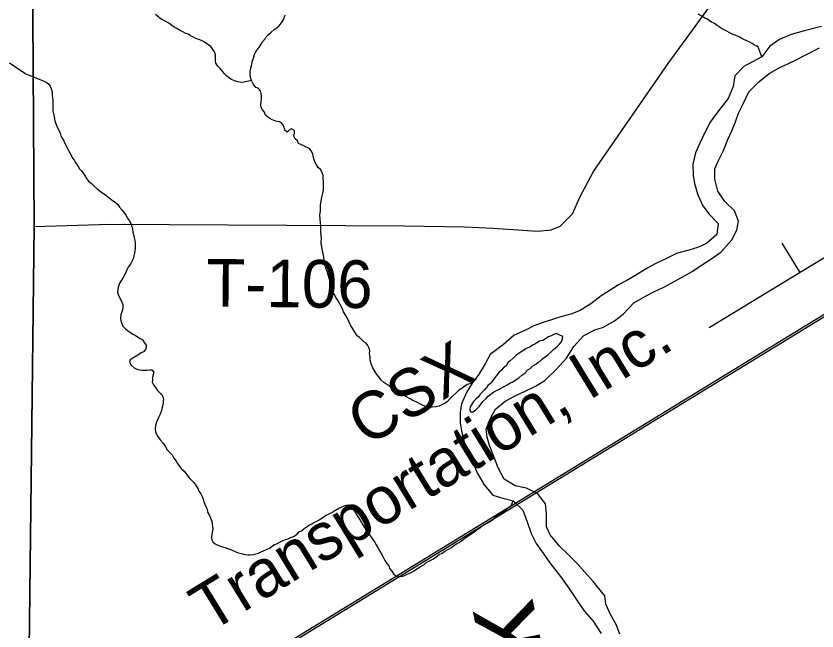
# Model space of a CAD drawing. Extents: x -7.3 to 34, y 0 to 22.
# Drawn here: x 2.725 to 3.68, y 18.213 to 18.947 of the extents above; entities that cross this region are included whole.
import ezdxf

# ---------------------------------------------------------------- set-up
doc = ezdxf.new("R2010")
doc.units = 0
for name, color, linetype in [('GM_X_Corporation', 7, 'Continuous'), ('GM_X_Major_River', 7, 'Continuous'), ('GM_X_Major_River_Text', 7, 'Continuous'), ('GM_X_Minor_River', 7, 'Continuous'), ('GM_X_Rail_Line', 7, 'Continuous'), ('GM_X_Rail_Line_Text', 7, 'Continuous'), ('GM_X_Township_Road', 7, 'Continuous'), ('GM_X_Township_Road_Text', 7, 'Continuous')]:
    doc.layers.add(name, color=color, linetype=linetype)

msp = doc.modelspace()

# ---------------------------------------------------------------- linework, layer by layer
at = {"layer": 'GM_X_Corporation'}
for points in [[(2.72526, 17.27857), (2.73186, 17.61235), (2.73309, 17.68446), (2.73436, 17.75863), (2.73656, 17.91355), (2.7405, 18.19145), (2.74664, 18.69646), (2.74012, 19.69659), (2.7402, 19.71066)], [(2.7402, 19.71066), (2.74012, 19.69659), (2.74664, 18.69646), (2.7405, 18.19145), (2.73656, 17.91355), (2.73436, 17.75863), (2.73309, 17.68446), (2.73186, 17.61235), (2.72526, 17.27857)], [(2.72526, 17.27857), (2.73186, 17.61235), (2.73309, 17.68446), (2.73436, 17.75863), (2.73656, 17.91355), (2.7405, 18.19145), (2.74664, 18.69646), (2.74012, 19.69659), (2.7402, 19.71066)], [(2.7402, 19.71066), (2.74012, 19.69659), (2.74664, 18.69646), (2.7405, 18.19145), (2.73656, 17.91355), (2.73436, 17.75863), (2.73309, 17.68446), (2.73186, 17.61235), (2.72526, 17.27857)]]:
    msp.add_lwpolyline(points, dxfattribs=at)
at = {"layer": 'GM_X_Major_River'}
for points in [[(3.68592, 18.93456), (3.67562, 18.93216), (3.66378, 18.92904), (3.64965, 18.92522), (3.63546, 18.91912), (3.62426, 18.91105), (3.61445, 18.89838), (3.6033, 18.89258), (3.59291, 18.88677), (3.58238, 18.87563), (3.58054, 18.86314), (3.57448, 18.84886)], [(3.44524, 18.2095), (3.44061, 18.22102), (3.43409, 18.23296), (3.42835, 18.24527), (3.4271, 18.25557), (3.41351, 18.27263), (3.40355, 18.28352), (3.39435, 18.29402), (3.38436, 18.30377), (3.37327, 18.3147), (3.36187, 18.32828), (3.35757, 18.3379), (3.35758, 18.3531), (3.35638, 18.36529), (3.34684, 18.37769), (3.33373, 18.38373), (3.32015, 18.38673), (3.30709, 18.39466), (3.30023, 18.40813), (3.2949, 18.42157), (3.28955, 18.43463), (3.28677, 18.44458), (3.28588, 18.45411), (3.29117, 18.46803), (3.29674, 18.47816), (3.30837, 18.48774), (3.32105, 18.49426), (3.33219, 18.49968), (3.34447, 18.50545), (3.35565, 18.51239), (3.36965, 18.52572), (3.38137, 18.53911), (3.39046, 18.55294), (3.40217, 18.56595), (3.41524, 18.57283), (3.42556, 18.57599), (3.43865, 18.58364), (3.44909, 18.59136), (3.46196, 18.6051), (3.47659, 18.61347), (3.48658, 18.61854), (3.49694, 18.62321), (3.51079, 18.63084), (3.52156, 18.63665), (3.53157, 18.64248), (3.54392, 18.65053), (3.55357, 18.65712), (3.56554, 18.66556), (3.57881, 18.68005), (3.5848, 18.69167), (3.5866, 18.70227), (3.58199, 18.71492), (3.57052, 18.72585), (3.56212, 18.73822), (3.55832, 18.75238), (3.55865, 18.76491), (3.56269, 18.77469), (3.56869, 18.78669), (3.57396, 18.79986), (3.57879, 18.81037), (3.58323, 18.8209), (3.58691, 18.83107), (3.59173, 18.84158), (3.59895, 18.8566), (3.61102, 18.86883), (3.62342, 18.87877), (3.63534, 18.88531), (3.65223, 18.89324), (3.66799, 18.9012), (3.68336, 18.90917)], [(3.57448, 18.84886), (3.56272, 18.83396), (3.55289, 18.82053), (3.5465, 18.80815), (3.54048, 18.79539), (3.53562, 18.78373), (3.53225, 18.77052), (3.53266, 18.75721), (3.5343, 18.74729), (3.53812, 18.73389), (3.54422, 18.72082), (3.55155, 18.71075), (3.56263, 18.69945), (3.56078, 18.68658), (3.54837, 18.67587), (3.53762, 18.67083), (3.5273, 18.66767), (3.51279, 18.66385), (3.50165, 18.65844), (3.48744, 18.65157), (3.47666, 18.64538), (3.46318, 18.63737), (3.45355, 18.63153), (3.44356, 18.62646), (3.43237, 18.61914), (3.42274, 18.61331), (3.41074, 18.60373), (3.39801, 18.59569), (3.3869, 18.59141), (3.37584, 18.58865), (3.36589, 18.58548), (3.3548, 18.58196), (3.34255, 18.57733), (3.33256, 18.57226), (3.31914, 18.56652), (3.30634, 18.55544), (3.29047, 18.5433), (3.28449, 18.53205), (3.27657, 18.51895), (3.26911, 18.50926), (3.26277, 18.49877), (3.25633, 18.48449), (3.25456, 18.47466), (3.2546, 18.46173), (3.25625, 18.45219), (3.25897, 18.43996), (3.26356, 18.42692), (3.27004, 18.41384), (3.2754, 18.40116), (3.2834, 18.38766), (3.2937, 18.37561), (3.30574, 18.37189), (3.31779, 18.36855), (3.32964, 18.3576), (3.33459, 18.3438), (3.33953, 18.32961), (3.34529, 18.31768), (3.35262, 18.30799), (3.36176, 18.29484), (3.37423, 18.27856), (3.38448, 18.26462), (3.39324, 18.25148), (3.40237, 18.23795), (3.41341, 18.22512), (3.42289, 18.21044)], [(3.36927, 18.56821), (3.36659, 18.56713), (3.36315, 18.56568), (3.36008, 18.56423), (3.35662, 18.56202), (3.35316, 18.5602), (3.34935, 18.55913), (3.34627, 18.5573), (3.34358, 18.55546), (3.3409, 18.55437), (3.33782, 18.55216), (3.33361, 18.55035), (3.33053, 18.54852), (3.32746, 18.54668), (3.32476, 18.54446), (3.32129, 18.54225), (3.31781, 18.53891), (3.31433, 18.53594), (3.31162, 18.53334), (3.30965, 18.52996), (3.30656, 18.52736), (3.30346, 18.52439), (3.30075, 18.52178), (3.29879, 18.51916), (3.29607, 18.5158), (3.29372, 18.51243), (3.29137, 18.50906), (3.2879, 18.50647), (3.28595, 18.50385), (3.28323, 18.50087), (3.2809, 18.49826), (3.27779, 18.4949), (3.27622, 18.49227), (3.27351, 18.49005), (3.2708, 18.48745), (3.26845, 18.48408), (3.26648, 18.4807), (3.26641, 18.47766), (3.26711, 18.47498), (3.26977, 18.47492), (3.27284, 18.47675), (3.27788, 18.48159), (3.27984, 18.48459), (3.28179, 18.48721), (3.28567, 18.49093), (3.288, 18.49354), (3.29147, 18.49612), (3.29494, 18.49871), (3.29801, 18.50055), (3.30146, 18.50199), (3.30415, 18.50345), (3.30799, 18.50565), (3.31067, 18.50712), (3.31413, 18.50894), (3.31758, 18.51077), (3.32027, 18.51261), (3.32451, 18.51556), (3.32837, 18.51852), (3.33184, 18.52111), (3.33533, 18.52484), (3.33803, 18.52668), (3.3415, 18.52965), (3.34496, 18.53185), (3.34767, 18.53407), (3.35036, 18.53592), (3.35307, 18.53814), (3.35615, 18.54035), (3.35963, 18.54332), (3.36311, 18.54667), (3.36659, 18.54963), (3.37007, 18.5526), (3.37278, 18.5552), (3.37551, 18.55857), (3.37672, 18.56196), (3.37716, 18.56462)], [(3.37716, 18.56462), (3.36927, 18.56821)]]:
    msp.add_lwpolyline(points, dxfattribs=at)
at = {"layer": 'GM_X_Minor_River'}
for points in [[(3.00562, 18.87042), (2.99723, 18.86832), (2.99381, 18.86802), (2.98965, 18.86849), (2.98551, 18.86972), (2.98213, 18.87131), (2.97876, 18.87329), (2.97615, 18.87562), (2.97356, 18.87834), (2.97135, 18.88143), (2.96838, 18.88454), (2.96578, 18.88726), (2.9632, 18.89073), (2.9629, 18.89416), (2.96296, 18.89682), (2.96267, 18.90101), (2.96161, 18.90445), (2.9594, 18.90792), (2.95719, 18.91063), (2.95346, 18.91376), (2.94897, 18.91652), (2.94597, 18.9181), (2.94296, 18.9193), (2.93958, 18.92052), (2.93657, 18.92173), (2.9332, 18.9237), (2.9302, 18.92567), (2.92757, 18.92648), (2.92382, 18.92847), (2.92082, 18.93005), (2.9167, 18.93242), (2.9137, 18.93401), (2.9107, 18.93597), (2.90735, 18.93871), (2.9021, 18.94148), (2.89797, 18.94347), (2.89387, 18.9466), (2.89126, 18.94894)], [(3.08865, 18.76368), (3.0853, 18.76641), (3.08347, 18.76949), (3.08164, 18.77258), (3.08021, 18.77679), (3.07953, 18.78023), (3.07883, 18.7829), (3.07701, 18.78637), (3.07479, 18.78908), (3.07178, 18.79028), (3.06803, 18.79226), (3.0654, 18.79346), (3.06202, 18.79505), (3.06057, 18.79813), (3.05797, 18.80047), (3.05615, 18.80393), (3.05698, 18.80733), (3.05705, 18.81075), (3.05368, 18.81273), (3.05099, 18.81127), (3.04828, 18.80866), (3.04568, 18.811), (3.04461, 18.81407), (3.04353, 18.81675), (3.0417, 18.81983), (3.03907, 18.82103), (3.03491, 18.82188), (3.03039, 18.82312), (3.02777, 18.8247), (3.02516, 18.82666), (3.02255, 18.82899), (3.02111, 18.83245), (3.01889, 18.83516), (3.01743, 18.83785), (3.01674, 18.84091), (3.01721, 18.84508), (3.01767, 18.84849), (3.01773, 18.85153), (3.01742, 18.85458), (3.01636, 18.85802), (3.01377, 18.86112), (3.01113, 18.86194), (3.00781, 18.86619), (3.00562, 18.87042), (3.00456, 18.87387), (3.00427, 18.87805), (3.00434, 18.88109), (3.00518, 18.88488), (3.00561, 18.88753), (3.00605, 18.89018), (3.00689, 18.89359), (3.0081, 18.89698), (3.00932, 18.90114), (3.01052, 18.90377), (3.01209, 18.9064), (3.01443, 18.90939), (3.01718, 18.91351), (3.01876, 18.91652), (3.02225, 18.91987), (3.02344, 18.9225), (3.02615, 18.9251), (3.02924, 18.9277), (3.03273, 18.93104), (3.03542, 18.9325), (3.03889, 18.93547), (3.04123, 18.93846), (3.04358, 18.94183), (3.04479, 18.94523), (3.04639, 18.94861)], [(3.61445, 18.89838), (3.60972, 18.91109), (3.60807, 18.9113), (3.60545, 18.91287), (3.60283, 18.91445), (3.60021, 18.91603), (3.59683, 18.91762), (3.59382, 18.91883), (3.59082, 18.92042), (3.5882, 18.92199), (3.58482, 18.92359), (3.58143, 18.9248), (3.57843, 18.92601), (3.57543, 18.92759), (3.57281, 18.92917), (3.56943, 18.93077), (3.56606, 18.93274), (3.56119, 18.93589), (3.55821, 18.93823), (3.55445, 18.93984), (3.5496, 18.94336), (3.54659, 18.94457), (3.54285, 18.94693), (3.53873, 18.9493)], [(2.73528, 18.87839), (2.71731, 18.89074)], [(2.73528, 18.87839), (2.7583, 18.86933), (2.76093, 18.86813), (2.76354, 18.86618), (2.76576, 18.86347), (2.76719, 18.85964), (2.76787, 18.85582), (2.76817, 18.85239), (2.7685, 18.84972), (2.76882, 18.84705), (2.76874, 18.84325), (2.76868, 18.84059), (2.76897, 18.83679), (2.76892, 18.83412), (2.76959, 18.83031), (2.77029, 18.82725), (2.77099, 18.82458), (2.77131, 18.82191), (2.77273, 18.81769), (2.77454, 18.81385), (2.776, 18.81078), (2.77744, 18.80733), (2.77851, 18.80426), (2.77997, 18.80157), (2.78179, 18.79811), (2.78324, 18.79503), (2.7847, 18.79234), (2.78615, 18.78927), (2.78761, 18.78657), (2.78907, 18.78388), (2.79053, 18.78119), (2.79235, 18.77772), (2.79419, 18.77502), (2.79602, 18.77232), (2.7986, 18.76846), (2.8008, 18.76499), (2.80339, 18.76189), (2.80522, 18.75919), (2.80743, 18.7561), (2.80889, 18.75341), (2.81148, 18.75031), (2.81445, 18.74759), (2.81817, 18.74408), (2.8219, 18.74096), (2.82525, 18.73823), (2.82824, 18.73626), (2.83197, 18.73352), (2.83608, 18.73038), (2.84018, 18.72725), (2.84317, 18.72491), (2.84577, 18.72257), (2.84835, 18.71909), (2.85169, 18.7156), (2.85353, 18.7129), (2.85574, 18.7098), (2.85756, 18.70634), (2.86014, 18.70287), (2.86196, 18.6994), (2.86302, 18.69596), (2.86372, 18.6929), (2.8644, 18.68946), (2.86509, 18.68641), (2.86577, 18.68259), (2.86646, 18.67953), (2.86715, 18.67609), (2.86707, 18.67267), (2.86701, 18.67001), (2.86658, 18.66736), (2.86613, 18.66433), (2.8653, 18.66092), (2.86484, 18.65751), (2.86327, 18.65488), (2.86129, 18.65112), (2.85856, 18.64738), (2.85697, 18.64437), (2.85577, 18.64136), (2.85418, 18.63797), (2.85261, 18.63534), (2.85064, 18.63196), (2.84829, 18.62859), (2.84747, 18.62595), (2.84666, 18.6233), (2.84622, 18.62065), (2.84615, 18.61761), (2.84686, 18.61493), (2.84793, 18.61224), (2.84975, 18.6084), (2.85121, 18.60571), (2.85229, 18.60302), (2.85221, 18.59922), (2.85177, 18.59657), (2.85056, 18.59317), (2.85012, 18.59052), (2.84967, 18.58711), (2.84997, 18.58368), (2.85103, 18.58023), (2.85248, 18.57716), (2.85545, 18.57405), (2.85807, 18.57209), (2.86143, 18.56974)], [(3.26911, 18.50926), (3.26289, 18.50739), (3.26019, 18.50555), (3.25711, 18.50334), (3.25287, 18.50039), (3.24978, 18.49779), (3.2463, 18.49444), (3.2428, 18.49072), (3.23969, 18.48736), (3.23699, 18.48514), (3.23355, 18.48369), (3.22971, 18.48149), (3.22552, 18.48082), (3.22134, 18.48053), (3.21868, 18.48021), (3.21453, 18.48106), (3.21077, 18.48267), (3.20663, 18.48428), (3.20288, 18.48626), (3.20026, 18.48784), (3.19763, 18.48904), (3.19501, 18.49062), (3.19051, 18.49299), (3.18602, 18.49575), (3.1834, 18.49771), (3.17966, 18.4997), (3.17591, 18.50168), (3.17217, 18.50442), (3.16881, 18.50678), (3.16619, 18.50835), (3.16357, 18.50993), (3.16022, 18.51305), (3.15801, 18.51614), (3.15543, 18.51962), (3.15322, 18.52271), (3.15067, 18.52733), (3.1485, 18.53232), (3.1478, 18.53499), (3.14748, 18.53766), (3.14717, 18.54109), (3.14648, 18.54415), (3.14694, 18.54794), (3.14625, 18.551), (3.14442, 18.55408), (3.14258, 18.55679), (3.13996, 18.55836), (3.13736, 18.5607), (3.13476, 18.56342), (3.13178, 18.56577), (3.12922, 18.57001), (3.12628, 18.57463), (3.12444, 18.57734), (3.12226, 18.58195), (3.12082, 18.5854), (3.11827, 18.59002), (3.11571, 18.59426), (3.11426, 18.59771), (3.11281, 18.60078), (3.11136, 18.60386), (3.1088, 18.6081), (3.10696, 18.6108), (3.10477, 18.61465), (3.10295, 18.61849), (3.10151, 18.62195), (3.10049, 18.62729), (3.09981, 18.63073), (3.09836, 18.63418), (3.09767, 18.63724), (3.09553, 18.64337), (3.09445, 18.64606), (3.09376, 18.64949), (3.09346, 18.65292), (3.0924, 18.65675), (3.09142, 18.664), (3.09034, 18.66668), (3.0897, 18.67202), (3.08901, 18.67507), (3.08907, 18.67773), (3.08915, 18.68154), (3.08887, 18.6861), (3.08855, 18.68916), (3.08865, 18.69334), (3.08833, 18.69638), (3.08804, 18.70057), (3.08776, 18.70514), (3.08748, 18.70971), (3.08797, 18.71464), (3.08804, 18.71806), (3.08813, 18.72187), (3.08898, 18.72641), (3.08942, 18.72906), (3.09025, 18.73247), (3.09108, 18.73587), (3.09154, 18.73966), (3.0916, 18.74232), (3.09168, 18.74612), (3.09176, 18.74954), (3.09146, 18.75335), (3.09116, 18.75678), (3.09009, 18.76023), (3.08865, 18.76368)], [(2.86143, 18.56974), (2.86442, 18.56777), (2.86704, 18.5662), (2.86965, 18.56424), (2.87227, 18.56266), (2.87565, 18.56068), (2.87785, 18.55759), (2.88006, 18.5545), (2.88001, 18.55184), (2.87919, 18.5492), (2.87686, 18.54659), (2.87417, 18.54512), (2.87147, 18.54328), (2.8684, 18.54145), (2.86417, 18.53887), (2.8611, 18.53704), (2.86027, 18.53402), (2.8621, 18.53055), (2.86582, 18.52743), (2.8692, 18.52583), (2.87222, 18.52501), (2.87486, 18.52457), (2.8779, 18.52451), (2.88094, 18.52482), (2.88436, 18.52512), (2.88701, 18.52507), (2.88923, 18.52236), (2.888, 18.5182), (2.88756, 18.51555), (2.88751, 18.51289), (2.88745, 18.51023), (2.8889, 18.50715), (2.89111, 18.50406), (2.89331, 18.50059), (2.8959, 18.49787), (2.89925, 18.49476), (2.90068, 18.49054), (2.90062, 18.48788), (2.90056, 18.48522), (2.89973, 18.48181), (2.89891, 18.47879), (2.89807, 18.47539), (2.89686, 18.47199), (2.89528, 18.46898), (2.89368, 18.46521), (2.89208, 18.46144), (2.89126, 18.4588), (2.8908, 18.45462), (2.89148, 18.45119), (2.89255, 18.44812), (2.89401, 18.44543), (2.89696, 18.44156), (2.90029, 18.43769), (2.90286, 18.43383), (2.90505, 18.42959), (2.90839, 18.42648), (2.91099, 18.42376), (2.91317, 18.41953), (2.91613, 18.41604), (2.91759, 18.41335), (2.92016, 18.40949), (2.92238, 18.40678), (2.92536, 18.40405), (2.92868, 18.3998), (2.93164, 18.39631), (2.93422, 18.39321), (2.9372, 18.39048), (2.93977, 18.38662), (2.94234, 18.38276), (2.94304, 18.38009), (2.94525, 18.37699), (2.94708, 18.37391), (2.94815, 18.37085), (2.94884, 18.36741), (2.95029, 18.36472), (2.95137, 18.36203), (2.95283, 18.35895), (2.9535, 18.35514), (2.95533, 18.35205), (2.95677, 18.3486), (2.95858, 18.34438), (2.95888, 18.34095), (2.9592, 18.3379), (2.95951, 18.33485), (2.95906, 18.33144), (2.95862, 18.32878), (2.95817, 18.32537), (2.95848, 18.32232), (2.95956, 18.31963), (2.96254, 18.31729), (2.96629, 18.3153), (2.9712, 18.31405), (2.97383, 18.31324), (2.97722, 18.31202), (2.98061, 18.31081), (2.98362, 18.3096), (2.987, 18.30801), (2.99001, 18.3068), (2.9934, 18.30597), (2.99793, 18.30473), (3.00133, 18.30427)], [(3.00133, 18.30427), (3.00398, 18.30422), (3.00778, 18.30452), (3.01084, 18.30559), (3.01427, 18.30628), (3.01734, 18.30773), (3.02002, 18.30919), (3.02461, 18.31099), (3.02807, 18.31282), (3.03231, 18.31615), (3.03499, 18.31724), (3.03882, 18.31905), (3.04227, 18.32088), (3.04686, 18.32268), (3.04954, 18.32339), (3.05337, 18.3252), (3.05604, 18.32629), (3.06027, 18.32886), (3.06261, 18.33185), (3.06529, 18.33293), (3.06877, 18.3359), (3.07223, 18.33811), (3.07493, 18.33995), (3.07761, 18.34141), (3.0803, 18.34288), (3.08374, 18.34432), (3.08644, 18.34617), (3.09105, 18.34873), (3.09414, 18.35132), (3.09758, 18.35277), (3.1018, 18.35496), (3.10526, 18.35717), (3.10988, 18.36011), (3.11293, 18.36119), (3.11561, 18.36227), (3.11868, 18.36372), (3.1221, 18.36403), (3.12583, 18.36091), (3.12765, 18.35782), (3.12949, 18.35512), (3.13131, 18.35166), (3.13389, 18.34818), (3.13535, 18.34548), (3.13719, 18.34278), (3.13865, 18.34009), (3.14121, 18.33585), (3.14342, 18.33276), (3.146, 18.32928), (3.14784, 18.32658), (3.15041, 18.32272), (3.15262, 18.31963), (3.15444, 18.31616), (3.15738, 18.31154), (3.15883, 18.30884), (3.16029, 18.30577), (3.16285, 18.30153), (3.16504, 18.29768), (3.16723, 18.29383), (3.16945, 18.29112), (3.17052, 18.28805), (3.17311, 18.28495), (3.17531, 18.28148), (3.17791, 18.27914), (3.18132, 18.27869), (3.18473, 18.27862), (3.1874, 18.27932), (3.19008, 18.2804), (3.19353, 18.28185), (3.19621, 18.28331), (3.1989, 18.28477), (3.20198, 18.28699), (3.20506, 18.28882), (3.20813, 18.29066), (3.2112, 18.29249), (3.21391, 18.29472), (3.2166, 18.29656), (3.21967, 18.29802), (3.22273, 18.29947), (3.2262, 18.30206), (3.22967, 18.30464), (3.23312, 18.30647), (3.23659, 18.30868), (3.24081, 18.31125), (3.24427, 18.31307), (3.24735, 18.31529), (3.25043, 18.3175), (3.2535, 18.31896), (3.25774, 18.32229), (3.26082, 18.32451), (3.26506, 18.32746), (3.26776, 18.3293), (3.27084, 18.33151), (3.27353, 18.33336), (3.27816, 18.33668), (3.28086, 18.3389), (3.28392, 18.34036), (3.287, 18.34219), (3.28968, 18.34366), (3.29354, 18.34662), (3.29625, 18.34884), (3.29894, 18.35068)], [(3.29894, 18.35068), (3.30165, 18.35291), (3.30587, 18.35548), (3.30856, 18.35694), (3.31204, 18.36029), (3.31551, 18.36287), (3.31779, 18.36855)]]:
    msp.add_lwpolyline(points, dxfattribs=at)
at = {"layer": 'GM_X_Rail_Line'}
for points in [[(2.74049, 18.00795), (3.31092, 18.35716), (4.03127, 18.798), (4.70203, 19.20884), (4.77741, 19.25463), (4.91095, 19.33597), (5.26231, 19.55109), (5.50449, 19.6986), (5.55332, 19.72923), (5.593, 19.75579), (5.62118, 19.77587), (5.64612, 19.79498), (5.68207, 19.82462), (5.70506, 19.84502), (5.72822, 19.86705), (5.74733, 19.88664), (5.76628, 19.90543), (5.79187, 19.93425), (5.81259, 19.95838), (5.8283, 19.97911), (5.85502, 20.01426)], [(2.77024, 18.02616), (2.79758, 18.04581), (3.30963, 18.35928), (4.02998, 18.80012), (4.70074, 19.21096), (4.77612, 19.25675), (4.88653, 19.324), (4.90447, 19.33202)]]:
    msp.add_lwpolyline(points, dxfattribs=at)
at = {"layer": 'GM_X_Township_Road'}
for p, q in [((2.74687, 18.69593), (2.74509, 18.9687)), ((2.74073, 18.19092), (2.74687, 18.69593)), ((3.66043, 18.64115), (3.63871, 18.67624))]:
    msp.add_line(p, q, dxfattribs=at)
for points in [[(2.74687, 18.69593), (2.83734, 18.69888), (3.18821, 18.69673), (3.25986, 18.69554), (3.29402, 18.69386), (3.3468, 18.69028), (3.36329, 18.69219), (3.3738, 18.69649), (3.38885, 18.71106), (3.39776, 18.73201), (3.41363, 18.76168), (3.50279, 18.89042), (3.57024, 18.98354), (3.61969, 19.05348), (3.63708, 19.08311), (3.6431, 19.09704), (3.64532, 19.11067), (3.6442, 19.12779), (3.64313, 19.14682), (3.63227, 19.20179), (3.64706, 19.36294), (3.65586, 19.38213), (3.67618, 19.40712), (3.6949, 19.42835)], [(3.77064, 18.67643), (3.73855, 18.67527), (3.72537, 18.67469), (3.715, 18.67236), (3.70153, 18.66635), (3.66043, 18.64115), (3.55175, 18.57502)]]:
    msp.add_lwpolyline(points, dxfattribs=at)

# ---------------------------------------------------------------- texts
at = {"layer": 'GM_X_Major_River_Text'}
msp.add_text('Creek', height=0.09478, rotation=101.30664, dxfattribs=at).set_placement((3.40723, 17.92063))
at = {"layer": 'GM_X_Rail_Line_Text'}
for s, height, rotation, p in [('Transportation, Inc.', 0.0566288, 31.50064, (2.95591, 18.2108)), ('CSX', 0.056629, 31.55684, (3.14335, 18.43259))]:
    msp.add_text(s, height=height, rotation=rotation, dxfattribs=at).set_placement(p)
at = {"layer": 'GM_X_Township_Road_Text'}
msp.add_text('T-106', height=0.056818, rotation=359.4386, dxfattribs=at).set_placement((2.95157, 18.6006))

doc.saveas('drawing.dxf')
